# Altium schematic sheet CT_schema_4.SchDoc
size 334 x 183 mm
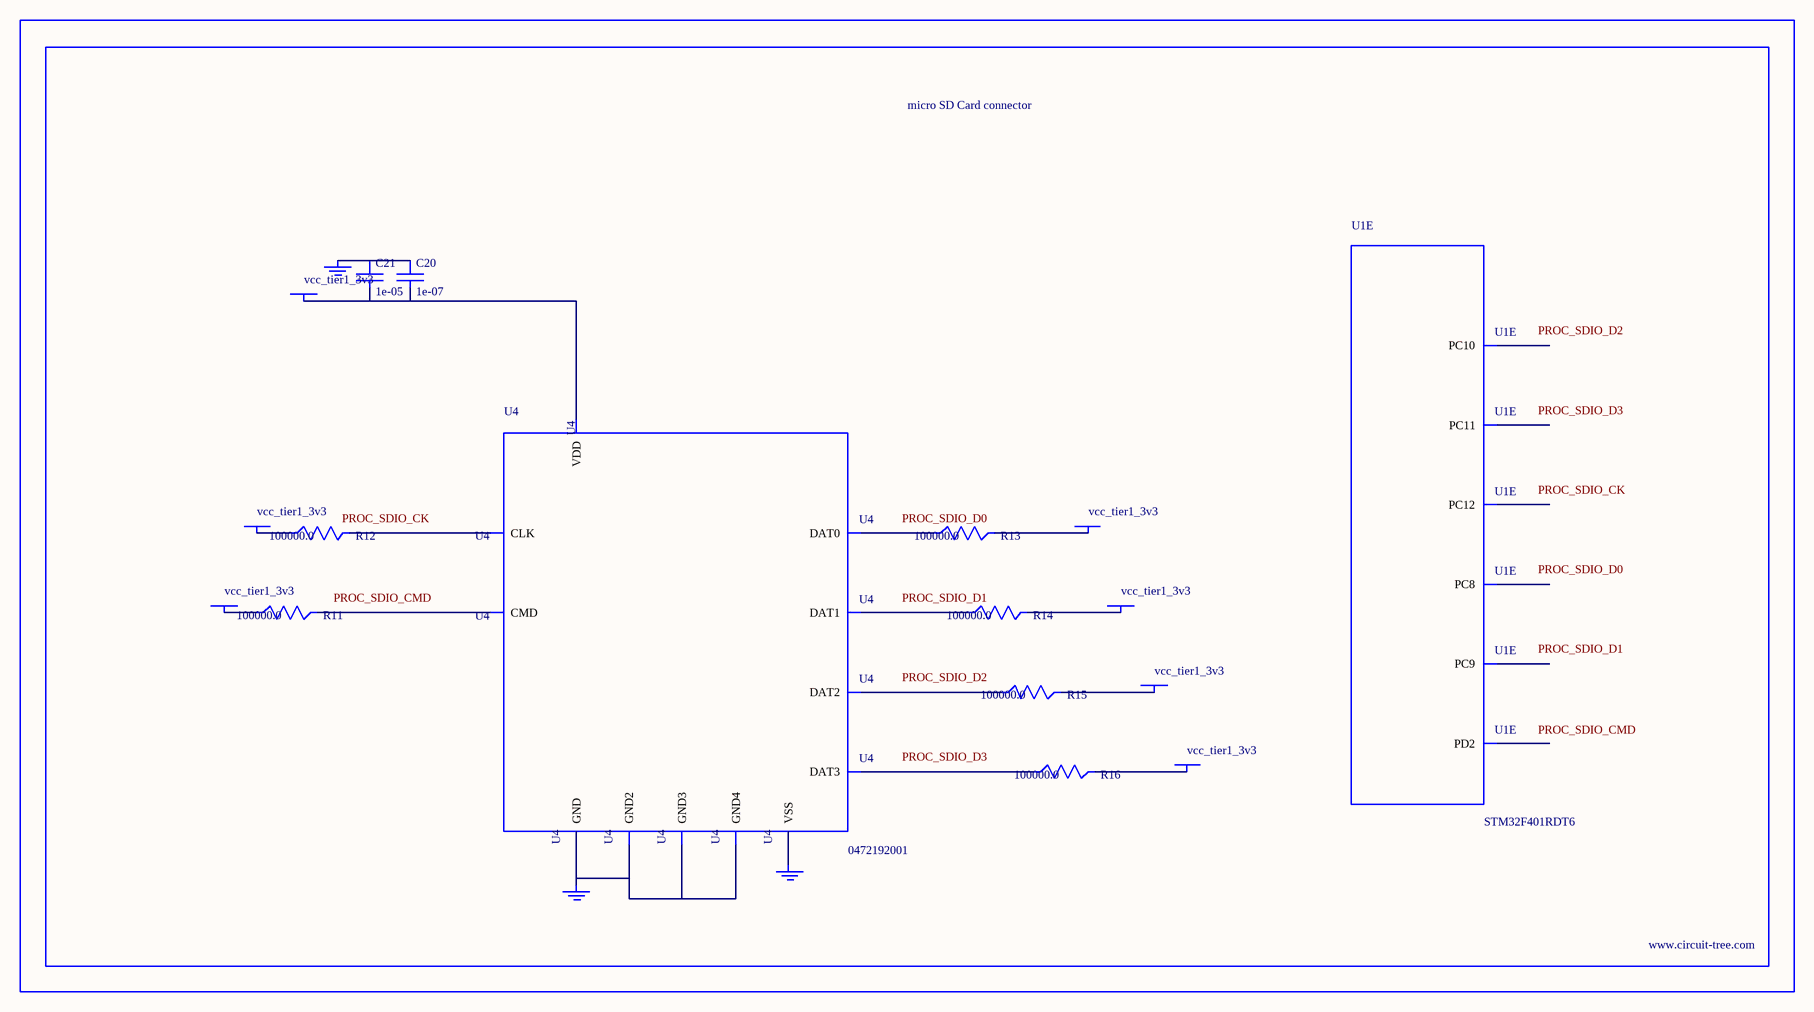
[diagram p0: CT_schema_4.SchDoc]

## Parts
BORDER3  (no value)
C20  1e-07  [C0402]
C21  1e-05  [C0805]
GND_INSTANCE_3_0  (no value)
GND_INSTANCE_3_1  (no value)
GND_INSTANCE_3_2  (no value)
POWER_INSTANCE_3_0  vcc_tier1_3v3
POWER_INSTANCE_3_1  vcc_tier1_3v3
POWER_INSTANCE_3_2  vcc_tier1_3v3
POWER_INSTANCE_3_3  vcc_tier1_3v3
POWER_INSTANCE_3_4  vcc_tier1_3v3
POWER_INSTANCE_3_5  vcc_tier1_3v3
POWER_INSTANCE_3_6  vcc_tier1_3v3
R11  100000.0  [R0603]
R12  100000.0  [R0603]
R13  100000.0  [R0603]
R14  100000.0  [R0603]
R15  100000.0  [R0603]
R16  100000.0  [R0603]
U1  STM32F401RDT6  [LQFP64]  (part E of 7)
U4  0472192001  [MOLEX_47219-2001]

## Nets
NetC20_1: C20.1 C21.1 GND_INSTANCE_3_0.0(GND)
NetC20_2: C20.2 C21.2 POWER_INSTANCE_3_3.0(PWR) U4.4(VDD)
NetGND_INSTANCE_3_1_0: GND_INSTANCE_3_1.0(GND) U4.6(VSS)
NetGND_INSTANCE_3_2_0: GND_INSTANCE_3_2.0(GND) U4.G1(GND) U4.G2(GND2) U4.G3(GND3) U4.G4(GND4)
NetPOWER_INSTANCE_3_0_0: POWER_INSTANCE_3_0.0(PWR) R15.2
NetPOWER_INSTANCE_3_1_0: POWER_INSTANCE_3_1.0(PWR) R16.2
NetPOWER_INSTANCE_3_2_0: POWER_INSTANCE_3_2.0(PWR) R11.1
NetPOWER_INSTANCE_3_4_0: POWER_INSTANCE_3_4.0(PWR) R12.1
NetPOWER_INSTANCE_3_5_0: POWER_INSTANCE_3_5.0(PWR) R13.2
NetPOWER_INSTANCE_3_6_0: POWER_INSTANCE_3_6.0(PWR) R14.2
NetR11_2: R11.2 U4.3(CMD)
NetR12_2: R12.2 U4.5(CLK)
NetR13_1: R13.1 U4.7(DAT0)
NetR14_1: R14.1 U4.8(DAT1)
NetR15_1: R15.1 U4.1(DAT2)
NetR16_1: R16.1 U4.2(DAT3)

Not connected (* = marked no-connect by the designer): U1 39(PC8) 40(PC9) 51(PC10) 52(PC11) 53(PC12) 54(PD2)

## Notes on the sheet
- Labels drawn without touching a wire or pin: PROC_SDIO_CK, PROC_SDIO_CMD, PROC_SDIO_D0, PROC_SDIO_D1, PROC_SDIO_D2, PROC_SDIO_D3

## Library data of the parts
BORDER3 = BORDER_PAGE3
C20 = C0402C104K3RACTU
C21 = C0805C106K8RACTU
GND_INSTANCE_3_0-GND_INSTANCE_3_2 = GND
POWER_INSTANCE_3_0-POWER_INSTANCE_3_6 = PWR
R11-R16 = RC0603JR-07100KL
